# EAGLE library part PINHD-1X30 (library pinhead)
PIN HEADER
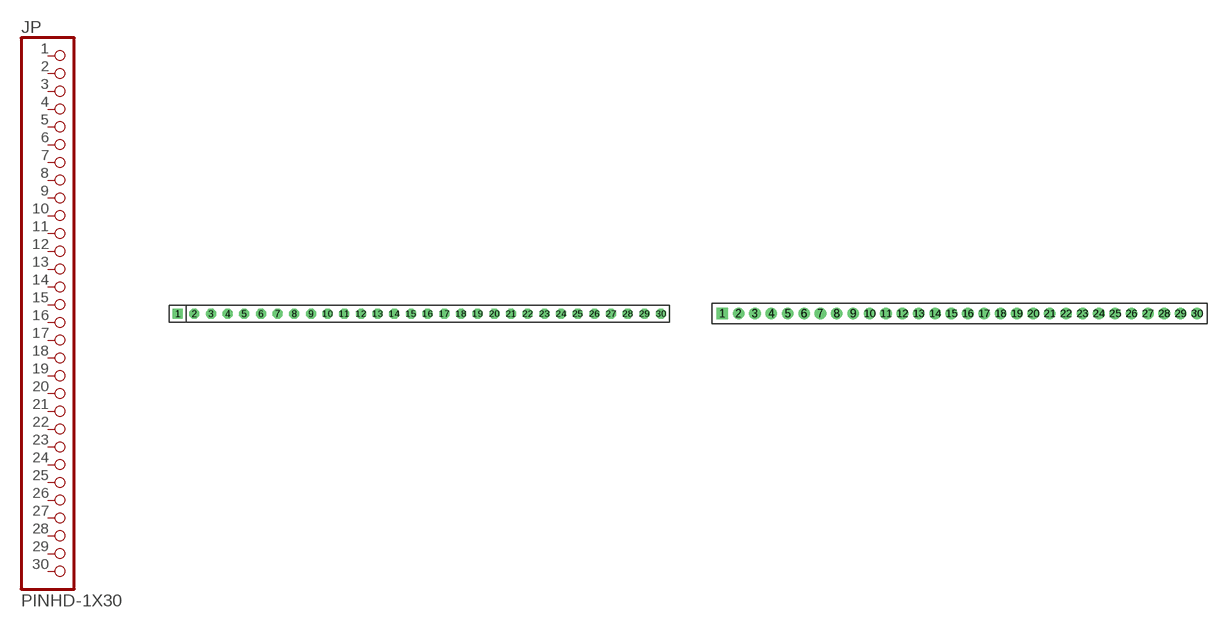
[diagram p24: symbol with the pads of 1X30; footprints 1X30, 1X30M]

Designator prefix JP

## PINHD-1X30  [1X30]
1  1  pas
2  2  pas
3  3  pas
4  4  pas
5  5  pas
6  6  pas
7  7  pas
8  8  pas
9  9  pas
10  10  pas
11  11  pas
12  12  pas
13  13  pas
14  14  pas
15  15  pas
16  16  pas
17  17  pas
18  18  pas
19  19  pas
20  20  pas
21  21  pas
22  22  pas
23  23  pas
24  24  pas
25  25  pas
26  26  pas
27  27  pas
28  28  pas
29  29  pas
30  30  pas

## PINHD-1X30M  [1X30M]
Pads as for 1X30

## Footprint 1X30 (pad centres in mm)
PIN HEADER - 0.1"
drill 1.016 square: 1 -36.83,0
drill 1.016 octagon: 2 -34.29,0; 3 -31.75,0; 4 -29.21,0; 5 -26.67,0; 6 -24.13,0; 7 -21.59,0; 8 -19.05,0; 9 -16.51,0; 10 -13.97,0; 11 -11.43,0; 12 -8.89,0; 13 -6.35,0; 14 -3.81,0; 15 -1.27,0; 16 1.27,0; 17 3.81,0; 18 6.35,0; 19 8.89,0; 20 11.43,0; 21 13.97,0; 22 16.51,0; 23 19.05,0; 24 21.59,0; 25 24.13,0; 26 26.67,0; 27 29.21,0; 28 31.75,0; 29 34.29,0; 30 36.83,0

## Footprint 1X30M (pad centres in mm)
PIN HEADER - 2MM"
drill 0.914 square: 1 -29,0
drill 0.914 round: 2 -27,0; 3 -25,0; 4 -23,0; 5 -21,0; 6 -19,0; 7 -17,0; 8 -15,0; 9 -13,0; 10 -11,0; 11 -9,0; 12 -7,0; 13 -5,0; 14 -3,0; 15 -1,0; 16 1,0; 17 3,0; 18 5,0; 19 7,0; 20 9,0; 21 11,0; 22 13,0; 23 15,0; 24 17,0; 25 19,0; 26 21,0; 27 23,0; 28 25,0; 29 27,0; 30 29,0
